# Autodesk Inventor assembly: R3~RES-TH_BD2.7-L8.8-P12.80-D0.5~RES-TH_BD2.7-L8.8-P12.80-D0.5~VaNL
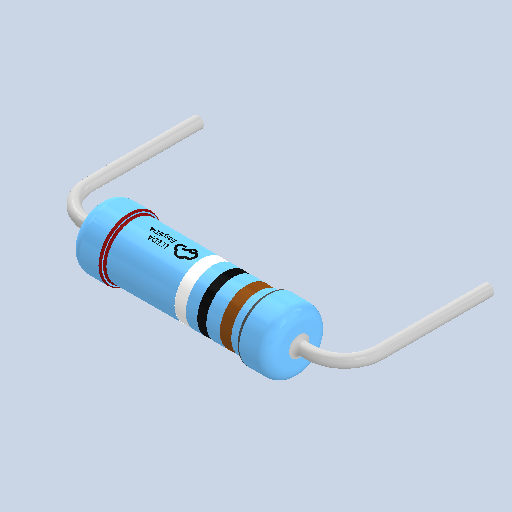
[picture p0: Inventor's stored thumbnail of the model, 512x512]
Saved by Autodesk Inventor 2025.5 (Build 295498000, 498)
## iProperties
Created: 2026-10
Part Number: R3~RES-TH_BD2.7-L8.8-P12.80-D0.5~RES-TH_BD2.7-L8.8-P12.80-D0.5~VaNL
Document SubType Name: Assembly
Designer: Luis M
Author: Luis M
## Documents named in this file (2)
- C:\Users\Luis M\Downloads\3D_PCB1_2026-10-28\R3~RES-TH_BD2.7-L8.8-P12.80-D0.5~RES-TH_BD2.7-L8.8-P12.80-D0.5~VaNL.iam
- C:\Users\Luis M\Downloads\3D_PCB1_2026-10-28\RES-TH_BD2.7-L8.8-P12.80-D0.5~RES-TH_BD2.7-L8.8-P12.80-D0.5~UAzC.ipt
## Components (1 placed, 1 different names)
1. R3->0
